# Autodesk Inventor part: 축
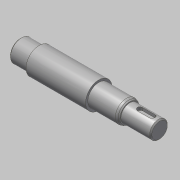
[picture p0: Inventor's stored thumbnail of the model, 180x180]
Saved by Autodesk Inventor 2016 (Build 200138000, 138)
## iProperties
Created: 2016-06
Part Number: 축
Material: 강철, 연강
Document SubType Name: Modeling
Designer: mduedu
Density: 7.86 g/cm^3
Appearance: 강철
Author: mduedu
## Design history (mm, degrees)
sketch "스케치1"
  geometry: L1 (-63, 0)-(63, 0); L2 (-63, 0)-(-63, 10); L3 (-63, 10)-(-46, 10); L4 (-46, 10)-(-46, 12); L5 (-46, 12)-(8, 12); L6 (8, 12)-(8, 10); L7 (8, 10)-(36, 10); L8 (36, 10)-(36, 8); L9 (36, 8)-(63, 8); L10 (63, 8)-(63, 0); 2 further points
  constraints: 20 end point, 5 parallel, 2 perpendicular, 1 coincident, 1 collinear, 1 horizontal, 1 midpoint, 1 vertical
  dimensions: "d0" = 126 distance of L1.start L1.end; "d2" = 16 diameter of L9 L1; "d3" = 20 diameter of L7 L1; "d4" = 24 diameter of L5 L1; "d5" = 20 diameter of L3 L1; "d6" = 17 distance of L2.end L3.end; "d7" = 27 distance of L8.end L9.end; "d8" = 55 distance from line of L5.end L10
revolve "회전1" sketch "스케치1" stored, may be unused: angle "d9" = 90 deg
chamfer "모따기1" distance "d10" = 2; stored, may be unused: second distance "d11" = 2, angle "d12" = 30 deg
fillet "모깎기1" dims "d13" = 4
node "작업 평면1"
sketch "스케치2"
  geometry: L1 (-4, 2.5)-(7, 2.5); L2 (7, -2.5)-(-4, -2.5); L3 (-4, 0)-(7, 0); L4 (-13.5, 8.845)-(-13.5, -8.845) reference; A1 r 2.5 centre (-4, 0) between (-4, 2.5) and (-4, -2.5); A2 r 2.5 centre (7, 0) between (7, -2.5) and (7, 2.5); 1 further point
  constraints: 6 end point, 4 point on circle, 3 tangent, 2 centre point, 2 parallel, 1 horizontal, 1 horizontal alignment
  dimensions: "d14" = 7 distance edge to line of A1 L4; "d15" = 5 distance between parallel lines of L2 L1; "d16" = 16 dimension on A2 A1
extrude "돌출1" cut sketch "스케치2" distance "d17" = 3; taper "d18" = 0 deg
chamfer "모따기2" distance "d19" = 1; stored, may be unused: second distance "d20" = 2, angle "d21" = 30 deg
sketch "스케치3"
  geometry: L1 (-36, -8)-(-62, -8) reference; L2 (-63, -7)-(-63, 7) reference; L3 (-39.5, -8)-(-41, -6.5); L4 (-41, -6.5)-(-41, -8); L5 (-39.5, -8)-(-41, -8); 1 further point
  constraints: 6 end point, 2 point on line, 1 collinear, 1 vertical
  dimensions: "d22" = 45 deg angle of L4 L3; "d23" = 22 distance between parallel lines of L2 L4; "d24" = 3 diameter of L3.start L4
revolve "회전2" stored, may be unused: angle "d25" = 90 deg
node "작업점1"
sketch "스케치4"
  geometry: 1 further point
hole "구멍1" sketch "스케치4" at (0, 0) diameter "d26" = 3.242; stored, may be unused: countersink angle "d30" = 90 deg, drill point angle "d32" = 120 deg; dims "d27" = 8, "d28" = 4, "d29" = 2, "d31" = 11
chamfer "모따기3" distance "d33" = 2; stored, may be unused: second distance "d34" = 2, angle "d35" = 30 deg
node "솔리드1"
